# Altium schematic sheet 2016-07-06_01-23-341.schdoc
size 298 x 111 mm; SheetNumber: 1; SheetTotal: 1
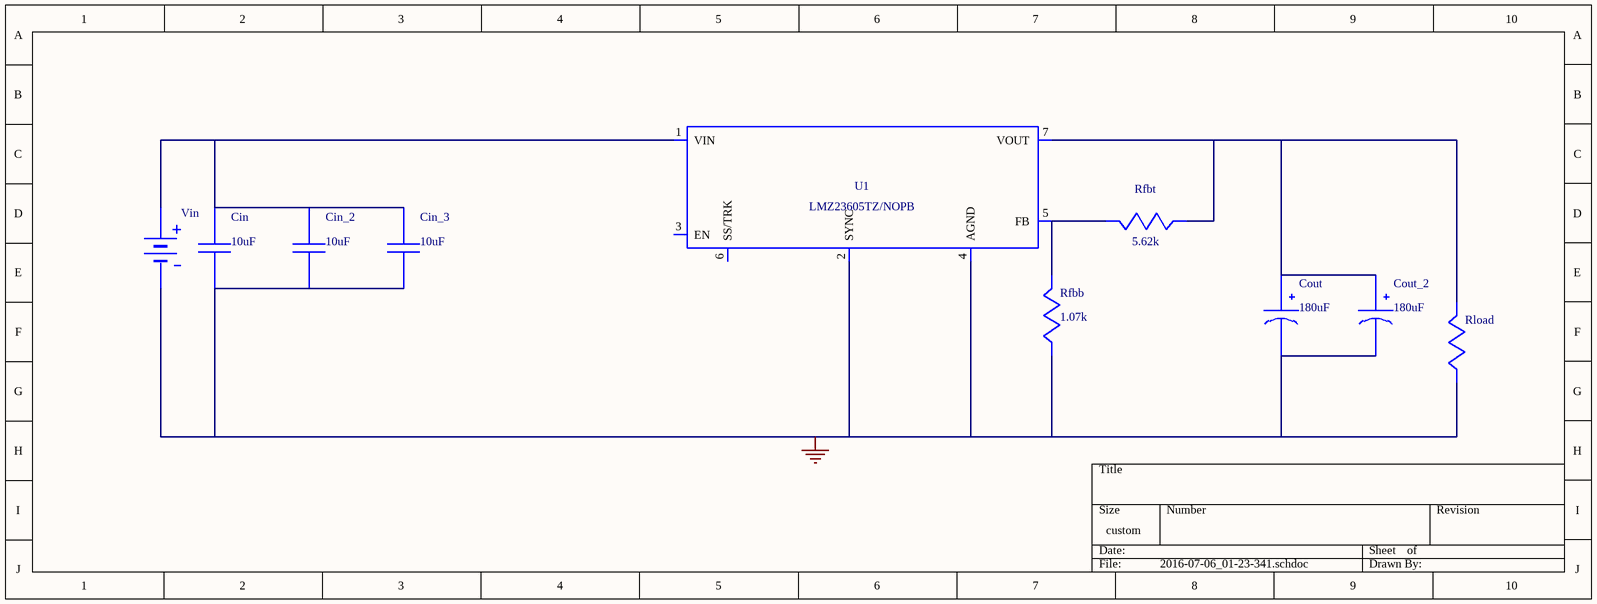
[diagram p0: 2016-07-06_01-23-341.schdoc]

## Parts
Cin  value 10uF  (hidden comment: GRM32ER7YA106KA12L)
Cin_2  value 10uF  (hidden comment: GRM32ER7YA106KA12L)
Cin_3  value 10uF  (hidden comment: GRM32ER7YA106KA12L)
Cout  value 180uF  (hidden comment: 16SVPF180M)
Cout_2  value 180uF  (hidden comment: 16SVPF180M)
Rfbb  value 1.07k  (hidden comment: ERJ-6ENF1071V)
Rfbt  value 5.62k  (hidden comment: ERJ-6ENF5621V)
Rload  WB_LOAD_RESISTOR  (value not drawn)
U1  LMZ23605TZ/NOPB
Vin  WB_BATTERY  (value not drawn)

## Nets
0: Cin.2 Cin_2.2 Cin_3.2 Cout.2(-) Cout_2.2(-) Rfbb.2 Rload.2 U1.2(SYNC) U1.4(AGND) U1.8(PGND/EP) Vin.2(-)
NetCin_1: Cin.1 Cin_2.1 Cin_3.1 U1.1(VIN) Vin.1(+)
NetCout_1: Cout.1(+) Cout_2.1(+) Rfbt.2 Rload.1 U1.7(VOUT)
NetRfbb_1: Rfbb.1 Rfbt.1 U1.5(FB)

Not connected (* = marked no-connect by the designer): U1 3(EN) 6(SS/TRK)

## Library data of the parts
Cin Cin_2 Cin_3 = GRM32ER7YA106KA12L: GRM32ER7YA106KA1; Manufacturer Name: MuRata
Cout Cout_2 = 16SVPF180M: Manufacturer Name: Panasonic
Rfbb = ERJ-6ENF1071V: Manufacturer Name: Panasonic
Rfbt = ERJ-6ENF5621V: Manufacturer Name: Panasonic
U1 = LMZ23605TZ/NOPB: Manufacturer Name: Texas Instruments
